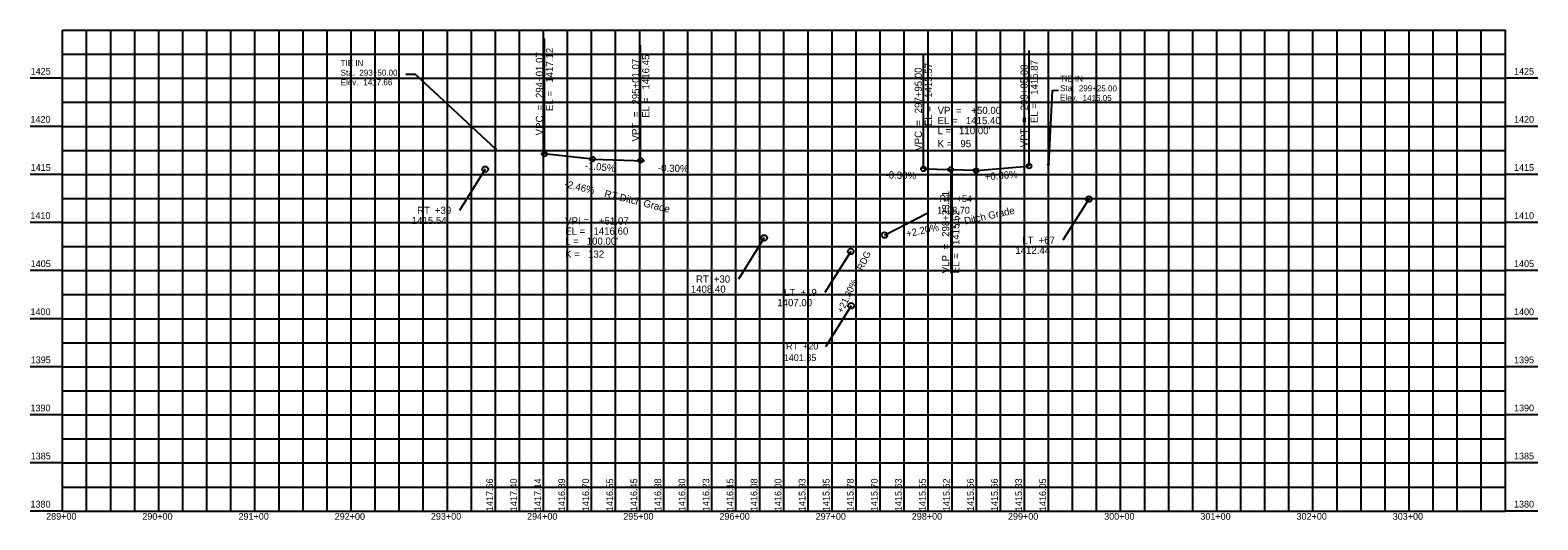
# Model space of a CAD drawing. Extents: x 2696 to 4263, y 1371 to 1880.
import ezdxf

# ---------------------------------------------------------------- set-up
doc = ezdxf.new("R2010")
doc.units = 0
for name, color, linetype in [('Alignment', 7, 'Continuous'), ('Default', 7, 'Continuous'), ('dsnNonPlotable', 7, 'Continuous'), ('TC_Grading', 7, 'Continuous'), ('TC_ShoulderEarthFill', 7, 'Continuous'), ('TC_SubgradeTreatment', 7, 'Continuous'), ('Terrain', 7, 'Continuous'), ('Text', 7, 'Continuous')]:
    doc.layers.add(name, color=color, linetype=linetype)

msp = doc.modelspace()

# ---------------------------------------------------------------- linework, layer by layer
at = {"layer": 'Default'}
for points in [[(3086.5, 1834.1), (3096.1, 1834.1), (3179.5, 1756.6)], [(3764.8, 1817.1), (3758.3, 1817), (3754.4, 1740.5)]]:
    msp.add_lwpolyline(points, dxfattribs=at)
at = {"layer": 'dsnNonPlotable'}
for p, q in [((3230.5, 1751.2), (3230.5, 1871.2)), ((3330.5, 1744.5), (3330.5, 1864.5)), ((3624.4, 1735.7), (3624.4, 1855.7)), ((3734.4, 1738.7), (3734.4, 1858.7)), ((3280.5, 1746), (3226.8, 1751.6)), ((3230.5, 1751.2), (3230.5, 1751.2)), ((3280.5, 1746), (3280.5, 1746)), ((3280.5, 1746), (3334.5, 1744.3)), ((3330.5, 1744.5), (3330.5, 1744.5)), ((3168.9, 1735.4), (3142.1, 1692.5)), ((3624.4, 1735.7), (3624.4, 1735.7)), ((3679.4, 1734), (3625.4, 1735.6)), ((3652.8, 1735.2), (3652.8, 1627.2)), ((3679.4, 1734), (3733.2, 1738.6)), ((3679.4, 1734), (3679.4, 1734)), ((3734.4, 1738.7), (3734.4, 1738.7)), ((3796.4, 1704.4), (3769.5, 1661.5)), ((3583.9, 1667), (3629, 1690)), ((3459, 1664), (3432.2, 1621.1)), ((3548.9, 1650), (3522.1, 1607.1)), ((3549.4, 1593.5), (3522.6, 1550.6))]:
    msp.add_line(p, q, dxfattribs=at)
for centre, radius in [((3168.9, 1735.4), 3), ((3652.8, 1735.2), 2.43), ((3796.4, 1704.4), 3), ((3459, 1664), 3), ((3583.9, 1667), 3), ((3548.9, 1650), 3), ((3549.4, 1593.5), 3)]:
    msp.add_circle(centre, radius, dxfattribs=at)
at = {"layer": 'TC_Grading'}
for p, q in [((2729.5, 1380), (2729.5, 1880)), ((2829.5, 1380), (2829.5, 1880)), ((2929.5, 1380), (2929.5, 1880)), ((3029.5, 1380), (3029.5, 1880)), ((3129.5, 1380), (3129.5, 1880)), ((3229.5, 1380), (3229.5, 1880)), ((3329.5, 1380), (3329.5, 1880)), ((3429.5, 1380), (3429.5, 1880)), ((3529.5, 1380), (3529.5, 1880)), ((3629.5, 1380), (3629.5, 1880)), ((3729.5, 1380), (3729.5, 1880)), ((3829.5, 1380), (3829.5, 1880)), ((3929.5, 1380), (3929.5, 1880)), ((4029.5, 1380), (4029.5, 1880)), ((4129.5, 1380), (4129.5, 1880)), ((2729.5, 1830), (2695.8, 1830)), ((2729.5, 1830), (4229.5, 1830)), ((4263.3, 1830), (4229.5, 1830)), ((2729.5, 1780), (2695.8, 1780)), ((2729.5, 1780), (4229.5, 1780)), ((4263.3, 1780), (4229.5, 1780)), ((2729.5, 1730), (2695.8, 1730)), ((2729.5, 1730), (4229.5, 1730)), ((4263.3, 1730), (4229.5, 1730)), ((2729.5, 1680), (2695.8, 1680)), ((2729.5, 1680), (4229.5, 1680)), ((4263.3, 1680), (4229.5, 1680)), ((2729.5, 1630), (2695.8, 1630)), ((2729.5, 1630), (4229.5, 1630)), ((4263.3, 1630), (4229.5, 1630)), ((2729.5, 1580), (2695.8, 1580)), ((2729.5, 1580), (4229.5, 1580)), ((4263.3, 1580), (4229.5, 1580)), ((2729.5, 1530), (2695.8, 1530)), ((2729.5, 1530), (4229.5, 1530)), ((4263.3, 1530), (4229.5, 1530)), ((2729.5, 1480), (2695.8, 1480)), ((2729.5, 1480), (4229.5, 1480)), ((4263.3, 1480), (4229.5, 1480)), ((2729.5, 1430), (2695.8, 1430)), ((2729.5, 1430), (4229.5, 1430)), ((4263.3, 1430), (4229.5, 1430)), ((2729.5, 1380), (2695.8, 1380)), ((4263.3, 1380), (4229.5, 1380))]:
    msp.add_line(p, q, dxfattribs=at)
at = {"layer": 'TC_ShoulderEarthFill'}
for p, q in [((2754.5, 1380), (2754.5, 1880)), ((2779.5, 1380), (2779.5, 1880)), ((2804.5, 1380), (2804.5, 1880)), ((2854.5, 1380), (2854.5, 1880)), ((2879.5, 1380), (2879.5, 1880)), ((2904.5, 1380), (2904.5, 1880)), ((2954.5, 1380), (2954.5, 1880)), ((2979.5, 1380), (2979.5, 1880)), ((3004.5, 1380), (3004.5, 1880)), ((3054.5, 1380), (3054.5, 1880)), ((3079.5, 1380), (3079.5, 1880)), ((3104.5, 1380), (3104.5, 1880)), ((3154.5, 1380), (3154.5, 1880)), ((3179.5, 1380), (3179.5, 1880)), ((3204.5, 1380), (3204.5, 1880)), ((3254.5, 1380), (3254.5, 1880)), ((3279.5, 1380), (3279.5, 1880)), ((3304.5, 1380), (3304.5, 1880)), ((3354.5, 1380), (3354.5, 1880)), ((3379.5, 1380), (3379.5, 1880)), ((3404.5, 1380), (3404.5, 1880)), ((3454.5, 1380), (3454.5, 1880)), ((3479.5, 1380), (3479.5, 1880)), ((3504.5, 1380), (3504.5, 1880)), ((3554.5, 1380), (3554.5, 1880)), ((3579.5, 1380), (3579.5, 1880)), ((3604.5, 1380), (3604.5, 1880)), ((3654.5, 1380), (3654.5, 1880)), ((3679.5, 1380), (3679.5, 1880)), ((3704.5, 1380), (3704.5, 1880)), ((3754.5, 1380), (3754.5, 1880)), ((3779.5, 1380), (3779.5, 1880)), ((3804.5, 1380), (3804.5, 1880)), ((3854.5, 1380), (3854.5, 1880)), ((3879.5, 1380), (3879.5, 1880)), ((3904.5, 1380), (3904.5, 1880)), ((3954.5, 1380), (3954.5, 1880)), ((3979.5, 1380), (3979.5, 1880)), ((4004.5, 1380), (4004.5, 1880)), ((4054.5, 1380), (4054.5, 1880)), ((4079.5, 1380), (4079.5, 1880)), ((4104.5, 1380), (4104.5, 1880)), ((4154.5, 1380), (4154.5, 1880)), ((4179.5, 1380), (4179.5, 1880)), ((4204.5, 1380), (4204.5, 1880)), ((2729.5, 1855), (4229.5, 1855)), ((2729.5, 1805), (4229.5, 1805)), ((2729.5, 1755), (4229.5, 1755)), ((2729.5, 1705), (4229.5, 1705)), ((2729.5, 1655), (4229.5, 1655)), ((2729.5, 1605), (4229.5, 1605)), ((2729.5, 1555), (4229.5, 1555)), ((2729.5, 1505), (4229.5, 1505)), ((2729.5, 1455), (4229.5, 1455)), ((2729.5, 1405), (4229.5, 1405))]:
    msp.add_line(p, q, dxfattribs=at)
at = {"layer": 'TC_SubgradeTreatment'}
for centre in [(3179.4, 1756.6), (3754.4, 1740.5)]:
    msp.add_circle(centre, 0.5, dxfattribs=at)
at = {"layer": 'Terrain'}
for p, q in [((2729.5, 1880), (4229.5, 1880)), ((2729.5, 1380), (2729.5, 1880)), ((4229.5, 1380), (4229.5, 1880)), ((2729.5, 1380), (4229.5, 1380))]:
    msp.add_line(p, q, dxfattribs=at)
at = {"layer": 'Text'}
for centre in [(3230.5, 1751.2), (3280.5, 1746), (3330.5, 1744.5), (3734.4, 1738.7), (3624.4, 1735.7), (3679.4, 1734)]:
    msp.add_circle(centre, 2.43, dxfattribs=at)

# ---------------------------------------------------------------- texts
at = {"layer": 'Alignment'}
for s, p in [('TIE IN', (3018.6, 1842.6)), ('Sta. ', (3018.6, 1832.6)), ('293+50.00', (3038, 1832.6)), ('Elev. ', (3018.6, 1822.7)), ('1417.66', (3042.1, 1822.7))]:
    msp.add_text(s, height=6.24, dxfattribs=at).set_placement(p)
for s, p in [('TIE IN', (3766.6, 1826.6)), ('Sta. ', (3766.5, 1816.6)), ('299+25.00', (3786, 1816.5)), ('Elev. ', (3766.5, 1806.6)), ('1416.05', (3790, 1806.4))]:
    msp.add_text(s, height=6.24, rotation=359.6588, dxfattribs=at).set_placement(p)
at = {"layer": 'dsnNonPlotable'}
for s, height, rotation, p in [('294+01.07', 7.5, 90, (3229, 1809.4)), ('1417.12', 7.5, 90, (3239.5, 1825.3)), ('295+01.07', 7.5, 90, (3329, 1802.6)), ('1416.45', 7.5, 90, (3339.5, 1818.3)), ('297+95.00', 7.5, 90, (3622.9, 1793.5)), ('1415.57', 7.5, 90, (3633.4, 1809.6)), ('299+05.00', 7.5, 90, (3732.9, 1796.6)), ('1415.87', 7.5, 90, (3743.4, 1812.7)), ('EL = ', 7.5, 90, (3239.5, 1795.9)), ('EL = ', 7.5, 90, (3339.5, 1788.9)), ('EL = ', 7.5, 90, (3743.4, 1783.3)), ('VPC', 7.5, 90, (3229, 1770.6)), (' = ', 7.5, 90, (3229, 1793.6)), (' = ', 7.5, 90, (3329, 1786.8)), ('EL = ', 7.5, 90, (3633.4, 1780.2)), (' = ', 7.5, 90, (3732.9, 1780.8)), ('VPT', 7.5, 90, (3329, 1764.3)), ('VPC', 7.5, 90, (3622.9, 1754.6)), (' = ', 7.5, 90, (3622.9, 1777.7)), ('VPT', 7.5, 90, (3732.9, 1758.3)), ('-1.05%', 7.5, 353.9781, (3272.2, 1735.8)), ('-0.30%', 7.5, 358.2816, (3348.4, 1733.1)), ('-0.30%', 7.5, 358.2816, (3585, 1725.9)), ('+0.86%', 7.5, 4.9241, (3688.5, 1723.8)), ('-2.46%', 7.5, 346.1713, (3250.7, 1716.9)), (' RT Ditch Grade', 7.5, 346.1713, (3289.5, 1707.4)), ('298+23.41', 7.5, 90, (3651.3, 1665.1)), (' LT Ditch Grade', 7.5, 12.4074, (3650.8, 1674.1)), ('+2.20%', 7.5, 12.4074, (3607.5, 1664.5)), ('1415.52', 7.5, 90, (3661.8, 1656.6)), (' RDG', 7.02, 64.8552, (3560.2, 1627.1)), (' = ', 7.5, 90, (3651.3, 1649.3)), ('EL = ', 7.5, 90, (3661.8, 1627.2)), ('VLP', 7.5, 90, (3651.3, 1627.2)), ('+21.30%', 7.02, 64.8552, (3540.5, 1585.2))]:
    msp.add_text(s, height=height, rotation=rotation, dxfattribs=at).set_placement(p)
for s, height, p in [('1425', 7.02, (2696.3, 1833.7)), ('1425', 7, (4238.5, 1833.7)), ('1420', 7.02, (2696.1, 1783.7)), ('VPI = ', 7.5, (3639.2, 1792.8)), ('EL = ', 7.5, (3639.2, 1782.3)), ('1415.40', 7.5, (3668.6, 1782.3)), ('+50.00', 7.5, (3674.3, 1792.8)), ('1420', 7, (4238.5, 1783.7)), ('L = ', 7.5, (3639.2, 1771.8)), ("110.00'", 7.5, (3661.5, 1771.8)), ('K = ', 7.5, (3639.2, 1758.3)), ('95', 7.5, (3662.9, 1758.3)), ('1415', 7.02, (2696.3, 1733.7)), ('1415', 7, (4238.5, 1733.7)), ('RT ', 7.5, (3098.1, 1688.9)), ('+39', 7.5, (3116.6, 1688.9)), ('1408.70', 7.02, (3638.8, 1689.3)), ('RT ', 7.02, (3641.2, 1701.3)), ('+54', 7.02, (3659, 1701.3)), ('1410', 7.02, (2696, 1683.7)), ('1415.54', 7.5, (3092.5, 1678.4)), ('VPI = ', 7.5, (3252, 1677.9)), ('+51.07', 7.5, (3287.1, 1677.9)), ('1410', 7, (4238.5, 1683.7)), ('EL = ', 7.5, (3252, 1667.4)), ('L = ', 7.5, (3252, 1656.9)), ("100.00'", 7.5, (3274.4, 1656.9)), ('1416.60', 7.5, (3281.4, 1667.4)), ('LT ', 7.5, (3727.1, 1657.9)), ('+67', 7.5, (3744.2, 1657.9)), ('K = ', 7.5, (3252, 1643.4)), ('132', 7.5, (3275.8, 1643.4)), ('1412.44', 7.5, (3720, 1647.4)), ('1405', 7.02, (2696.3, 1633.7)), ('1405', 7, (4238.5, 1633.7)), ('1408.40', 7.5, (3382.6, 1607)), ('RT ', 7.5, (3388, 1617.5)), ('+30', 7.5, (3406.5, 1617.5)), ('1407.00', 7.5, (3472.5, 1593)), ('LT ', 7.5, (3479.5, 1603.5)), ('+19', 7.5, (3496.6, 1603.5)), ('1400', 7.02, (2696.1, 1583.7)), ('1400', 7, (4238.5, 1583.7)), ('RT ', 7.02, (3481.6, 1548)), ('+20', 7.02, (3499.3, 1548)), ('1395', 7.02, (2696.3, 1533.7)), ('1401.35', 7.02, (3479.2, 1536)), ('1395', 7, (4238.5, 1533.7)), ('1390', 7.02, (2696.1, 1483.7)), ('1390', 7, (4238.5, 1483.7)), ('1385', 7.02, (2696.3, 1433.7)), ('1385', 7, (4238.5, 1433.7)), ('1380', 7.02, (2696.1, 1383.7)), ('1380', 7, (4238.5, 1383.7)), ('289+00', 7, (2712.4, 1371)), ('290+00', 7, (2812.4, 1371)), ('291+00', 7, (2912.4, 1371)), ('292+00', 7, (3012.4, 1371)), ('293+00', 7, (3112.4, 1371)), ('294+00', 7, (3212.4, 1371)), ('295+00', 7, (3312.4, 1371)), ('296+00', 7, (3412.4, 1371)), ('297+00', 7, (3512.4, 1371)), ('298+00', 7, (3612.4, 1371)), ('299+00', 7, (3712.4, 1371)), ('300+00', 7, (3812.4, 1371)), ('301+00', 7, (3912.4, 1371)), ('302+00', 7, (4012.4, 1371)), ('303+00', 7, (4112.4, 1371))]:
    msp.add_text(s, height=height, dxfattribs=at).set_placement(p)
at = {"layer": 'Text'}
for s, p in [('1417.66', (3177, 1380)), ('1417.40', (3202, 1380)), ('1417.14', (3227, 1380)), ('1416.89', (3252, 1380)), ('1416.70', (3276.9, 1380)), ('1416.55', (3301.9, 1380)), ('1416.45', (3326.9, 1380)), ('1416.38', (3351.9, 1380)), ('1416.30', (3376.9, 1380)), ('1416.23', (3401.9, 1380)), ('1416.15', (3426.9, 1380)), ('1416.08', (3451.9, 1380)), ('1416.00', (3476.9, 1380)), ('1415.93', (3501.9, 1380)), ('1415.85', (3526.9, 1380)), ('1415.78', (3551.9, 1380)), ('1415.70', (3576.9, 1380)), ('1415.63', (3601.9, 1380)), ('1415.55', (3626.9, 1380)), ('1415.52', (3651.9, 1380)), ('1415.56', (3676.9, 1380)), ('1415.66', (3701.9, 1380)), ('1415.83', (3726.9, 1380)), ('1416.05', (3752, 1380)), ('1416.05', (3752, 1380))]:
    msp.add_text(s, height=7.02, rotation=90, dxfattribs=at).set_placement(p)

doc.saveas('drawing.dxf')
